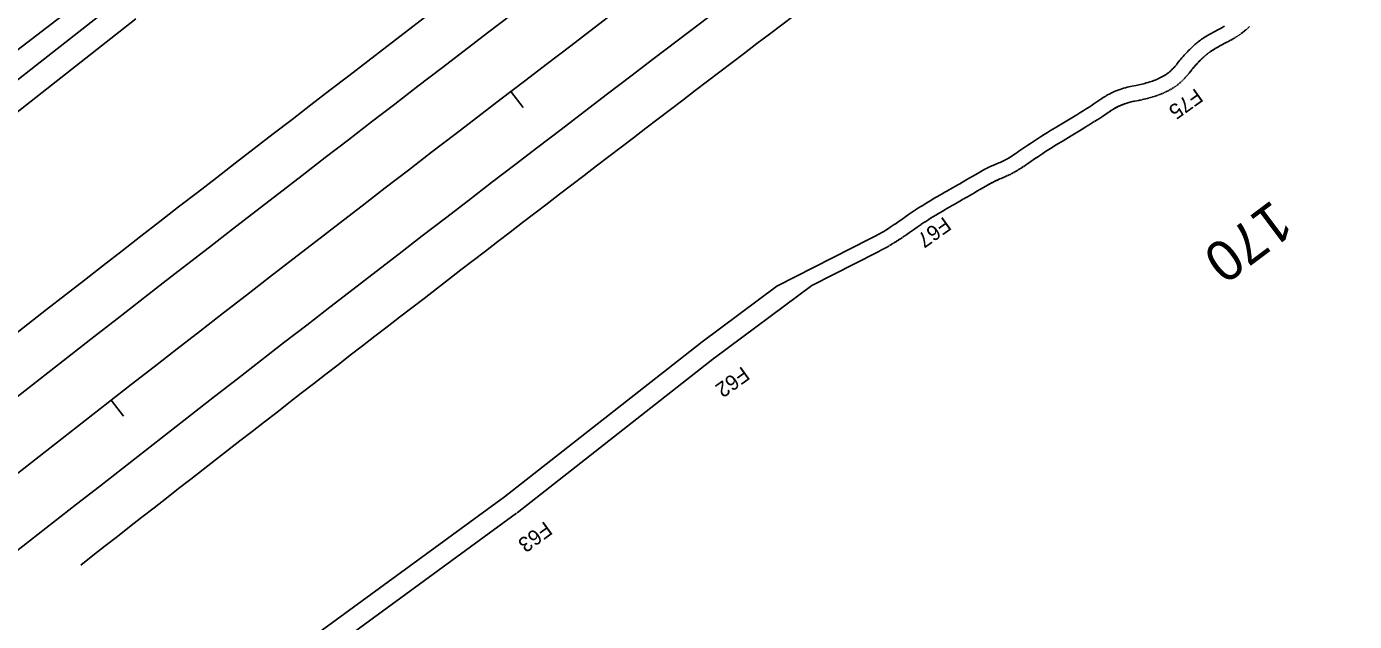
# Model space of a CAD drawing. Extents: x 1469024 to 1473560, y 1105695 to 1109739.
# Drawn here: x 1470861.2 to 1471124.1, y 1107470.7 to 1107588.4 of the extents above; entities that cross this region are included whole.
import ezdxf

# ---------------------------------------------------------------- set-up
doc = ezdxf.new("R2010")
doc.units = 0
for name, color, linetype in [('RD_HC_CL_Rel', 7, 'Continuous'), ('RD_HC_Data_Tic_Rel', 7, 'Continuous'), ('RD_HC_TX_Rel_Sta50', 7, 'Continuous'), ('RD_PD_CstnLmt', 7, 'Continuous'), ('RD_PD_CstnLmt_TX', 7, 'Continuous'), ('RD_PD_DR_Ditch', 7, 'Continuous'), ('RD_PD_DR_ErosCtrl', 7, 'Continuous'), ('RD_PD_Final_TrvlWay', 7, 'Continuous'), ('RD_PD_GR', 7, 'Continuous'), ('RD_PD_RW', 7, 'Continuous')]:
    doc.layers.add(name, color=color, linetype=linetype)

msp = doc.modelspace()

# ---------------------------------------------------------------- linework, layer by layer
at = {"layer": 'RD_HC_CL_Rel'}
msp.add_arc((1477943.58, 1098441.09), 11500, 126.41418, 130.102414, dxfattribs=at)
at = {"layer": 'RD_HC_Data_Tic_Rel'}
for p, q in [((1470957.06, 1107575.56), (1470959.49, 1107572.38)), ((1470877.89, 1107514.46), (1470880.35, 1107511.31))]:
    msp.add_line(p, q, dxfattribs=at)
at = {"layer": 'RD_PD_CstnLmt'}
for p, q in [((1470837.12, 1107566.82), (1470877.09, 1107597.35)), ((1471098.39, 1107588.48), (1471098.12, 1107588.33)), ((1471093.63, 1107585.74), (1471093.38, 1107585.56)), ((1471093.84, 1107585.89), (1471093.63, 1107585.74)), ((1471094.06, 1107586.04), (1471093.84, 1107585.89)), ((1471094.3, 1107586.2), (1471094.06, 1107586.04)), ((1471094.55, 1107586.36), (1471094.3, 1107586.2)), ((1471094.8, 1107586.52), (1471094.55, 1107586.36)), ((1471094.98, 1107586.62), (1471094.8, 1107586.52)), ((1471095.15, 1107586.72), (1471094.98, 1107586.62)), ((1471095.33, 1107586.82), (1471095.15, 1107586.72)), ((1471095.71, 1107587.03), (1471095.33, 1107586.82)), ((1471096.18, 1107587.28), (1471095.71, 1107587.03)), ((1471097.29, 1107587.88), (1471096.18, 1107587.28)), ((1471097.85, 1107588.17), (1471097.29, 1107587.88)), ((1471098.12, 1107588.33), (1471097.85, 1107588.17)), ((1471090.81, 1107583.2), (1471090.6, 1107582.97)), ((1471091.03, 1107583.43), (1471090.81, 1107583.2)), ((1471091.25, 1107583.65), (1471091.03, 1107583.43)), ((1471091.47, 1107583.87), (1471091.25, 1107583.65)), ((1471091.69, 1107584.08), (1471091.47, 1107583.87)), ((1471091.89, 1107584.28), (1471091.69, 1107584.08)), ((1471092.09, 1107584.47), (1471091.89, 1107584.28)), ((1471092.29, 1107584.65), (1471092.09, 1107584.47)), ((1471092.49, 1107584.83), (1471092.29, 1107584.65)), ((1471092.69, 1107585), (1471092.49, 1107584.83)), ((1471092.89, 1107585.16), (1471092.69, 1107585)), ((1471093.01, 1107585.27), (1471092.89, 1107585.16)), ((1471093.14, 1107585.37), (1471093.01, 1107585.27)), ((1471093.38, 1107585.56), (1471093.14, 1107585.37)), ((1471088.52, 1107580.49), (1471088.38, 1107580.33)), ((1471088.65, 1107580.65), (1471088.52, 1107580.49)), ((1471088.83, 1107580.86), (1471088.65, 1107580.65)), ((1471089.01, 1107581.08), (1471088.83, 1107580.86)), ((1471089.54, 1107581.74), (1471089.01, 1107581.08)), ((1471089.72, 1107581.97), (1471089.54, 1107581.74)), ((1471089.94, 1107582.23), (1471089.72, 1107581.97)), ((1471090.16, 1107582.48), (1471089.94, 1107582.23)), ((1471090.39, 1107582.74), (1471090.16, 1107582.48)), ((1471090.6, 1107582.97), (1471090.39, 1107582.74)), ((1471084.89, 1107577.93), (1471084.61, 1107577.81)), ((1471085.2, 1107578.06), (1471084.89, 1107577.93)), ((1471085.45, 1107578.18), (1471085.2, 1107578.06)), ((1471085.7, 1107578.3), (1471085.45, 1107578.18)), ((1471085.95, 1107578.43), (1471085.7, 1107578.3)), ((1471086.2, 1107578.56), (1471085.95, 1107578.43)), ((1471086.45, 1107578.7), (1471086.2, 1107578.56)), ((1471086.57, 1107578.78), (1471086.45, 1107578.7)), ((1471086.69, 1107578.85), (1471086.57, 1107578.78)), ((1471086.81, 1107578.93), (1471086.69, 1107578.85)), ((1471086.93, 1107579.01), (1471086.81, 1107578.93)), ((1471087.04, 1107579.09), (1471086.93, 1107579.01)), ((1471087.16, 1107579.18), (1471087.04, 1107579.09)), ((1471087.27, 1107579.26), (1471087.16, 1107579.18)), ((1471087.38, 1107579.35), (1471087.27, 1107579.26)), ((1471087.49, 1107579.44), (1471087.38, 1107579.35)), ((1471087.6, 1107579.54), (1471087.49, 1107579.44)), ((1471087.7, 1107579.63), (1471087.6, 1107579.54)), ((1471087.81, 1107579.73), (1471087.7, 1107579.63)), ((1471087.95, 1107579.87), (1471087.81, 1107579.73)), ((1471088.09, 1107580.02), (1471087.95, 1107579.87)), ((1471088.24, 1107580.17), (1471088.09, 1107580.02)), ((1471088.38, 1107580.33), (1471088.24, 1107580.17)), ((1471075.99, 1107575.28), (1471075.78, 1107575.18)), ((1471076.2, 1107575.38), (1471075.99, 1107575.28)), ((1471076.4, 1107575.47), (1471076.2, 1107575.38)), ((1471076.61, 1107575.56), (1471076.4, 1107575.47)), ((1471076.87, 1107575.66), (1471076.61, 1107575.56)), ((1471077.13, 1107575.77), (1471076.87, 1107575.66)), ((1471077.41, 1107575.87), (1471077.13, 1107575.77)), ((1471077.72, 1107575.98), (1471077.41, 1107575.87)), ((1471078.05, 1107576.09), (1471077.72, 1107575.98)), ((1471078.39, 1107576.2), (1471078.05, 1107576.09)), ((1471078.74, 1107576.3), (1471078.39, 1107576.2)), ((1471079.09, 1107576.39), (1471078.74, 1107576.3)), ((1471079.44, 1107576.48), (1471079.09, 1107576.39)), ((1471079.72, 1107576.54), (1471079.44, 1107576.48)), ((1471080, 1107576.6), (1471079.72, 1107576.54)), ((1471080.84, 1107576.75), (1471080, 1107576.6)), ((1471081.12, 1107576.81), (1471080.84, 1107576.75)), ((1471081.43, 1107576.87), (1471081.12, 1107576.81)), ((1471081.73, 1107576.94), (1471081.43, 1107576.87)), ((1471082.03, 1107577.01), (1471081.73, 1107576.94)), ((1471082.32, 1107577.08), (1471082.03, 1107577.01)), ((1471082.61, 1107577.16), (1471082.32, 1107577.08)), ((1471082.88, 1107577.24), (1471082.61, 1107577.16)), ((1471083.22, 1107577.34), (1471082.88, 1107577.24)), ((1471083.55, 1107577.44), (1471083.22, 1107577.34)), ((1471083.87, 1107577.54), (1471083.55, 1107577.44)), ((1471084.09, 1107577.62), (1471083.87, 1107577.54)), ((1471084.36, 1107577.72), (1471084.09, 1107577.62)), ((1471084.61, 1107577.81), (1471084.36, 1107577.72)), ((1471071.95, 1107572.75), (1471071.54, 1107572.48)), ((1471072.52, 1107573.13), (1471071.95, 1107572.75)), ((1471073.68, 1107573.9), (1471072.52, 1107573.13)), ((1471074.1, 1107574.19), (1471073.68, 1107573.9)), ((1471074.35, 1107574.34), (1471074.1, 1107574.19)), ((1471074.59, 1107574.5), (1471074.35, 1107574.34)), ((1471074.84, 1107574.66), (1471074.59, 1107574.5)), ((1471075.09, 1107574.8), (1471074.84, 1107574.66)), ((1471075.34, 1107574.95), (1471075.09, 1107574.8)), ((1471075.56, 1107575.06), (1471075.34, 1107574.95)), ((1471075.78, 1107575.18), (1471075.56, 1107575.06)), ((1471068.13, 1107570.36), (1471066.47, 1107569.36)), ((1471069.12, 1107570.96), (1471068.13, 1107570.36)), ((1471069.75, 1107571.35), (1471069.12, 1107570.96)), ((1471070.38, 1107571.74), (1471069.75, 1107571.35)), ((1471070.98, 1107572.12), (1471070.38, 1107571.74)), ((1471071.54, 1107572.48), (1471070.98, 1107572.12)), ((1471063.34, 1107567.47), (1471062.64, 1107567.03)), ((1471063.93, 1107567.83), (1471063.34, 1107567.47)), ((1471064.85, 1107568.39), (1471063.93, 1107567.83)), ((1471066.47, 1107569.36), (1471064.85, 1107568.39)), ((1471059.45, 1107564.95), (1471057.65, 1107563.72)), ((1471060.12, 1107565.4), (1471059.45, 1107564.95)), ((1471060.73, 1107565.81), (1471060.12, 1107565.4)), ((1471061.31, 1107566.19), (1471060.73, 1107565.81)), ((1471061.96, 1107566.61), (1471061.31, 1107566.19)), ((1471062.64, 1107567.03), (1471061.96, 1107566.61)), ((1471055.18, 1107562.15), (1471054.98, 1107562.04)), ((1471055.37, 1107562.26), (1471055.18, 1107562.15)), ((1471055.58, 1107562.38), (1471055.37, 1107562.26)), ((1471055.9, 1107562.57), (1471055.58, 1107562.38)), ((1471056.23, 1107562.78), (1471055.9, 1107562.57)), ((1471056.58, 1107563), (1471056.23, 1107562.78)), ((1471056.93, 1107563.23), (1471056.58, 1107563)), ((1471057.29, 1107563.47), (1471056.93, 1107563.23)), ((1471057.65, 1107563.72), (1471057.29, 1107563.47)), ((1471049.61, 1107559.43), (1471048.55, 1107558.83)), ((1471050.28, 1107559.8), (1471049.61, 1107559.43)), ((1471050.61, 1107559.99), (1471050.28, 1107559.8)), ((1471050.94, 1107560.16), (1471050.61, 1107559.99)), ((1471051.27, 1107560.34), (1471050.94, 1107560.16)), ((1471051.59, 1107560.5), (1471051.27, 1107560.34)), ((1471051.73, 1107560.57), (1471051.59, 1107560.5)), ((1471052.02, 1107560.71), (1471051.73, 1107560.57)), ((1471052.3, 1107560.84), (1471052.02, 1107560.71)), ((1471052.7, 1107561.01), (1471052.3, 1107560.84)), ((1471052.95, 1107561.12), (1471052.7, 1107561.01)), ((1471053.7, 1107561.44), (1471052.95, 1107561.12)), ((1471053.94, 1107561.54), (1471053.7, 1107561.44)), ((1471054.19, 1107561.65), (1471053.94, 1107561.54)), ((1471054.44, 1107561.77), (1471054.19, 1107561.65)), ((1471054.71, 1107561.9), (1471054.44, 1107561.77)), ((1471054.98, 1107562.04), (1471054.71, 1107561.9)), ((1471045.22, 1107556.89), (1471044.49, 1107556.48)), ((1471045.59, 1107557.11), (1471045.22, 1107556.89)), ((1471045.95, 1107557.32), (1471045.59, 1107557.11)), ((1471047.34, 1107558.13), (1471045.95, 1107557.32)), ((1471047.83, 1107558.42), (1471047.34, 1107558.13)), ((1471048.55, 1107558.83), (1471047.83, 1107558.42)), ((1471041.03, 1107554.49), (1471040.08, 1107553.92)), ((1471041.51, 1107554.77), (1471041.03, 1107554.49)), ((1471042, 1107555.06), (1471041.51, 1107554.77)), ((1471042.49, 1107555.34), (1471042, 1107555.06)), ((1471042.97, 1107555.62), (1471042.49, 1107555.34)), ((1471043.36, 1107555.84), (1471042.97, 1107555.62)), ((1471044.49, 1107556.48), (1471043.36, 1107555.84)), ((1471036.58, 1107551.73), (1471036.19, 1107551.46)), ((1471036.99, 1107552), (1471036.58, 1107551.73)), ((1471037.39, 1107552.26), (1471036.99, 1107552)), ((1471037.8, 1107552.52), (1471037.39, 1107552.26)), ((1471038.21, 1107552.78), (1471037.8, 1107552.52)), ((1471038.61, 1107553.03), (1471038.21, 1107552.78)), ((1471039.08, 1107553.31), (1471038.61, 1107553.03)), ((1471040.08, 1107553.92), (1471039.08, 1107553.31)), ((1471032.57, 1107548.95), (1471032.18, 1107548.69)), ((1471032.96, 1107549.21), (1471032.57, 1107548.95)), ((1471033.36, 1107549.47), (1471032.96, 1107549.21)), ((1471033.76, 1107549.75), (1471033.36, 1107549.47)), ((1471034.27, 1107550.1), (1471033.76, 1107549.75)), ((1471035.03, 1107550.64), (1471034.27, 1107550.1)), ((1471035.8, 1107551.19), (1471035.03, 1107550.64)), ((1471036.19, 1107551.46), (1471035.8, 1107551.19)), ((1471028.16, 1107546.38), (1471009.75, 1107537.03)), ((1471028.55, 1107546.59), (1471028.16, 1107546.38)), ((1471028.94, 1107546.79), (1471028.55, 1107546.59)), ((1471029.31, 1107546.99), (1471028.94, 1107546.79)), ((1471029.68, 1107547.2), (1471029.31, 1107546.99)), ((1471030.04, 1107547.39), (1471029.68, 1107547.2)), ((1471030.48, 1107547.65), (1471030.04, 1107547.39)), ((1471030.89, 1107547.89), (1471030.48, 1107547.65)), ((1471031.29, 1107548.14), (1471030.89, 1107547.89)), ((1471031.8, 1107548.45), (1471031.29, 1107548.14)), ((1471032.18, 1107548.69), (1471031.8, 1107548.45)), ((1471009.75, 1107537.03), (1470994.94, 1107526.04)), ((1470994.94, 1107526.04), (1470955.81, 1107495.34)), ((1470955.81, 1107495.34), (1470915.62, 1107466.03))]:
    msp.add_line(p, q, dxfattribs=at)
at = {"layer": 'RD_PD_DR_Ditch'}
for p, q in [((1470840.22, 1107562.84), (1470879.75, 1107593.9)), ((1470843.29, 1107558.9), (1470882.8, 1107589.94))]:
    msp.add_line(p, q, dxfattribs=at)
at = {"layer": 'RD_PD_DR_ErosCtrl'}
for p, q in [((1471103.33, 1107588.39), (1471102.89, 1107588)), ((1471099.86, 1107585.86), (1471099.59, 1107585.71)), ((1471100.06, 1107585.97), (1471099.89, 1107585.88)), ((1471100.25, 1107586.09), (1471100.08, 1107585.99)), ((1471100.44, 1107586.2), (1471100.27, 1107586.1)), ((1471100.63, 1107586.32), (1471100.47, 1107586.22)), ((1471100.82, 1107586.44), (1471100.66, 1107586.34)), ((1471101.02, 1107586.57), (1471100.86, 1107586.46)), ((1471101.21, 1107586.7), (1471101.06, 1107586.59)), ((1471101.41, 1107586.83), (1471101.25, 1107586.73)), ((1471101.6, 1107586.97), (1471101.44, 1107586.86)), ((1471101.79, 1107587.11), (1471101.63, 1107587)), ((1471101.98, 1107587.26), (1471101.82, 1107587.14)), ((1471102.17, 1107587.41), (1471102.01, 1107587.28)), ((1471102.31, 1107587.52), (1471102.2, 1107587.43)), ((1471102.58, 1107587.75), (1471102.35, 1107587.55)), ((1471102.86, 1107587.98), (1471102.62, 1107587.77)), ((1471095.22, 1107583.19), (1471094.98, 1107583)), ((1471095.42, 1107583.33), (1471095.17, 1107583.15)), ((1471095.59, 1107583.45), (1471095.37, 1107583.3)), ((1471095.77, 1107583.58), (1471095.55, 1107583.43)), ((1471095.96, 1107583.71), (1471095.72, 1107583.55)), ((1471096.16, 1107583.83), (1471095.92, 1107583.68)), ((1471096.37, 1107583.96), (1471096.12, 1107583.8)), ((1471096.5, 1107584.04), (1471096.33, 1107583.93)), ((1471096.65, 1107584.12), (1471096.48, 1107584.02)), ((1471096.81, 1107584.21), (1471096.63, 1107584.11)), ((1471097.16, 1107584.4), (1471096.78, 1107584.2)), ((1471097.6, 1107584.64), (1471097.13, 1107584.39)), ((1471098.7, 1107585.23), (1471097.58, 1107584.63)), ((1471099.27, 1107585.53), (1471098.72, 1107585.24)), ((1471099.57, 1107585.7), (1471099.29, 1107585.55)), ((1471092.44, 1107580.53), (1471092.21, 1107580.27)), ((1471092.63, 1107580.75), (1471092.41, 1107580.5)), ((1471092.82, 1107580.95), (1471092.61, 1107580.72)), ((1471093, 1107581.15), (1471092.79, 1107580.92)), ((1471093.2, 1107581.35), (1471092.98, 1107581.12)), ((1471093.39, 1107581.55), (1471093.17, 1107581.33)), ((1471093.59, 1107581.74), (1471093.37, 1107581.53)), ((1471093.78, 1107581.94), (1471093.56, 1107581.72)), ((1471093.96, 1107582.11), (1471093.76, 1107581.92)), ((1471094.14, 1107582.28), (1471093.94, 1107582.09)), ((1471094.32, 1107582.44), (1471094.12, 1107582.25)), ((1471094.49, 1107582.59), (1471094.29, 1107582.41)), ((1471094.66, 1107582.73), (1471094.46, 1107582.56)), ((1471094.82, 1107582.87), (1471094.62, 1107582.7)), ((1471094.91, 1107582.95), (1471094.79, 1107582.84)), ((1471095.01, 1107583.03), (1471094.89, 1107582.93)), ((1471090.25, 1107577.93), (1471090.1, 1107577.78)), ((1471090.43, 1107578.13), (1471090.29, 1107577.97)), ((1471090.61, 1107578.32), (1471090.47, 1107578.17)), ((1471090.78, 1107578.52), (1471090.64, 1107578.36)), ((1471090.94, 1107578.71), (1471090.8, 1107578.55)), ((1471091.14, 1107578.95), (1471090.97, 1107578.74)), ((1471091.34, 1107579.19), (1471091.16, 1107578.97)), ((1471091.88, 1107579.86), (1471091.34, 1107579.2)), ((1471092.04, 1107580.07), (1471091.86, 1107579.84)), ((1471092.24, 1107580.3), (1471092.02, 1107580.04)), ((1471086.38, 1107575.31), (1471086.08, 1107575.17)), ((1471086.69, 1107575.45), (1471086.44, 1107575.33)), ((1471087, 1107575.59), (1471086.75, 1107575.47)), ((1471087.32, 1107575.75), (1471087.06, 1107575.62)), ((1471087.63, 1107575.92), (1471087.38, 1107575.79)), ((1471087.95, 1107576.1), (1471087.7, 1107575.96)), ((1471088.13, 1107576.21), (1471088.01, 1107576.14)), ((1471088.29, 1107576.32), (1471088.17, 1107576.24)), ((1471088.45, 1107576.42), (1471088.33, 1107576.34)), ((1471088.62, 1107576.53), (1471088.5, 1107576.45)), ((1471088.78, 1107576.65), (1471088.66, 1107576.56)), ((1471088.94, 1107576.76), (1471088.83, 1107576.68)), ((1471089.1, 1107576.89), (1471088.99, 1107576.8)), ((1471089.26, 1107577.01), (1471089.15, 1107576.92)), ((1471089.41, 1107577.14), (1471089.3, 1107577.05)), ((1471089.57, 1107577.27), (1471089.46, 1107577.18)), ((1471089.72, 1107577.41), (1471089.61, 1107577.31)), ((1471089.87, 1107577.55), (1471089.76, 1107577.45)), ((1471090.06, 1107577.73), (1471089.91, 1107577.59)), ((1471077.32, 1107572.59), (1471077.1, 1107572.48)), ((1471077.47, 1107572.66), (1471077.27, 1107572.57)), ((1471077.63, 1107572.73), (1471077.42, 1107572.64)), ((1471077.79, 1107572.8), (1471077.58, 1107572.71)), ((1471078, 1107572.89), (1471077.74, 1107572.78)), ((1471078.22, 1107572.97), (1471077.95, 1107572.87)), ((1471078.45, 1107573.06), (1471078.17, 1107572.95)), ((1471078.72, 1107573.15), (1471078.41, 1107573.04)), ((1471079.01, 1107573.25), (1471078.68, 1107573.14)), ((1471079.29, 1107573.34), (1471078.95, 1107573.23)), ((1471079.58, 1107573.42), (1471079.23, 1107573.32)), ((1471079.86, 1107573.5), (1471079.52, 1107573.4)), ((1471080.14, 1107573.56), (1471079.79, 1107573.48)), ((1471080.36, 1107573.61), (1471080.08, 1107573.55)), ((1471080.59, 1107573.65), (1471080.31, 1107573.6)), ((1471081.39, 1107573.8), (1471080.55, 1107573.65)), ((1471081.69, 1107573.86), (1471081.41, 1107573.81)), ((1471082.04, 1107573.93), (1471081.73, 1107573.87)), ((1471082.39, 1107574.01), (1471082.09, 1107573.94)), ((1471082.73, 1107574.09), (1471082.43, 1107574.02)), ((1471083.06, 1107574.18), (1471082.77, 1107574.1)), ((1471083.38, 1107574.26), (1471083.1, 1107574.19)), ((1471083.69, 1107574.35), (1471083.41, 1107574.27)), ((1471084.07, 1107574.46), (1471083.72, 1107574.36)), ((1471084.44, 1107574.57), (1471084.11, 1107574.47)), ((1471084.8, 1107574.69), (1471084.49, 1107574.59)), ((1471085.07, 1107574.79), (1471084.85, 1107574.71)), ((1471085.38, 1107574.9), (1471085.12, 1107574.8)), ((1471085.68, 1107575.01), (1471085.43, 1107574.92)), ((1471086.02, 1107575.15), (1471085.74, 1107575.03)), ((1471073.16, 1107569.96), (1471072.6, 1107569.6)), ((1471073.59, 1107570.23), (1471073.18, 1107569.97)), ((1471074.18, 1107570.62), (1471073.6, 1107570.24)), ((1471075.35, 1107571.41), (1471074.19, 1107570.64)), ((1471075.76, 1107571.69), (1471075.33, 1107571.4)), ((1471075.98, 1107571.83), (1471075.74, 1107571.67)), ((1471076.2, 1107571.97), (1471075.96, 1107571.81)), ((1471076.42, 1107572.1), (1471076.17, 1107571.95)), ((1471076.63, 1107572.23), (1471076.38, 1107572.08)), ((1471076.83, 1107572.34), (1471076.58, 1107572.2)), ((1471076.99, 1107572.43), (1471076.78, 1107572.31)), ((1471077.16, 1107572.51), (1471076.94, 1107572.4)), ((1471069.67, 1107567.79), (1471068.02, 1107566.79)), ((1471070.68, 1107568.4), (1471069.68, 1107567.79)), ((1471071.33, 1107568.8), (1471070.69, 1107568.41)), ((1471071.97, 1107569.2), (1471071.34, 1107568.81)), ((1471072.58, 1107569.59), (1471071.99, 1107569.21)), ((1471064.93, 1107564.92), (1471064.23, 1107564.49)), ((1471065.5, 1107565.28), (1471064.91, 1107564.91)), ((1471066.41, 1107565.82), (1471065.49, 1107565.27)), ((1471068.02, 1107566.79), (1471066.4, 1107565.82)), ((1471061.14, 1107562.47), (1471059.34, 1107561.24)), ((1471061.8, 1107562.92), (1471061.13, 1107562.46)), ((1471062.39, 1107563.31), (1471061.79, 1107562.91)), ((1471062.95, 1107563.68), (1471062.37, 1107563.3)), ((1471063.59, 1107564.08), (1471062.93, 1107563.66)), ((1471064.24, 1107564.5), (1471063.57, 1107564.07)), ((1471056.6, 1107559.51), (1471056.41, 1107559.4)), ((1471056.84, 1107559.64), (1471056.65, 1107559.53)), ((1471057.09, 1107559.78), (1471056.88, 1107559.66)), ((1471057.45, 1107560), (1471057.13, 1107559.81)), ((1471057.83, 1107560.24), (1471057.49, 1107560.03)), ((1471058.21, 1107560.48), (1471057.86, 1107560.26)), ((1471058.58, 1107560.73), (1471058.23, 1107560.5)), ((1471058.96, 1107560.98), (1471058.6, 1107560.74)), ((1471059.33, 1107561.23), (1471058.97, 1107560.99)), ((1471051.1, 1107556.82), (1471050.04, 1107556.22)), ((1471051.74, 1107557.19), (1471051.08, 1107556.82)), ((1471052.05, 1107557.36), (1471051.72, 1107557.18)), ((1471052.36, 1107557.52), (1471052.03, 1107557.35)), ((1471052.66, 1107557.68), (1471052.33, 1107557.51)), ((1471052.95, 1107557.82), (1471052.62, 1107557.66)), ((1471053.06, 1107557.88), (1471052.91, 1107557.81)), ((1471053.31, 1107558), (1471053.03, 1107557.86)), ((1471053.55, 1107558.11), (1471053.27, 1107557.98)), ((1471053.91, 1107558.27), (1471053.51, 1107558.09)), ((1471054.13, 1107558.36), (1471053.88, 1107558.25)), ((1471054.87, 1107558.67), (1471054.12, 1107558.36)), ((1471055.13, 1107558.79), (1471054.89, 1107558.68)), ((1471055.41, 1107558.91), (1471055.16, 1107558.8)), ((1471055.71, 1107559.05), (1471055.46, 1107558.93)), ((1471056.03, 1107559.2), (1471055.76, 1107559.07)), ((1471056.36, 1107559.37), (1471056.09, 1107559.24)), ((1471046.71, 1107554.29), (1471045.97, 1107553.87)), ((1471047.09, 1107554.51), (1471046.72, 1107554.3)), ((1471047.46, 1107554.73), (1471047.1, 1107554.51)), ((1471048.86, 1107555.54), (1471047.47, 1107554.73)), ((1471049.34, 1107555.82), (1471048.84, 1107555.53)), ((1471050.05, 1107556.23), (1471049.33, 1107555.81)), ((1471042.57, 1107551.91), (1471041.62, 1107551.35)), ((1471043.04, 1107552.19), (1471042.56, 1107551.9)), ((1471043.52, 1107552.47), (1471043.03, 1107552.18)), ((1471043.99, 1107552.75), (1471043.5, 1107552.46)), ((1471044.47, 1107553.02), (1471043.98, 1107552.74)), ((1471044.84, 1107553.23), (1471044.46, 1107553.01)), ((1471045.96, 1107553.86), (1471044.83, 1107553.23)), ((1471037.91, 1107549), (1471037.51, 1107548.72)), ((1471038.28, 1107549.25), (1471037.88, 1107548.98)), ((1471038.65, 1107549.5), (1471038.25, 1107549.23)), ((1471039.03, 1107549.75), (1471038.62, 1107549.48)), ((1471039.41, 1107549.99), (1471039.01, 1107549.73)), ((1471039.8, 1107550.24), (1471039.39, 1107549.98)), ((1471040.19, 1107550.48), (1471039.78, 1107550.23)), ((1471040.64, 1107550.75), (1471040.18, 1107550.47)), ((1471041.64, 1107551.35), (1471040.63, 1107550.75)), ((1471034.2, 1107546.43), (1471033.81, 1107546.18)), ((1471034.61, 1107546.7), (1471034.22, 1107546.44)), ((1471035.03, 1107546.98), (1471034.64, 1107546.72)), ((1471035.45, 1107547.27), (1471035.05, 1107547)), ((1471035.98, 1107547.64), (1471035.47, 1107547.28)), ((1471036.76, 1107548.19), (1471036, 1107547.65)), ((1471037.53, 1107548.74), (1471036.76, 1107548.19)), ((1471029.52, 1107543.71), (1471016.65, 1107537.17)), ((1471029.93, 1107543.92), (1471029.54, 1107543.72)), ((1471030.34, 1107544.14), (1471029.95, 1107543.93)), ((1471030.74, 1107544.35), (1471030.36, 1107544.15)), ((1471031.13, 1107544.57), (1471030.76, 1107544.36)), ((1471031.51, 1107544.78), (1471031.15, 1107544.58)), ((1471031.98, 1107545.05), (1471031.54, 1107544.79)), ((1471032.42, 1107545.31), (1471032.01, 1107545.07)), ((1471032.85, 1107545.57), (1471032.44, 1107545.33)), ((1471033.39, 1107545.91), (1471032.88, 1107545.59)), ((1471033.79, 1107546.16), (1471033.41, 1107545.92)), ((1471016.65, 1107537.17), (1470997.32, 1107522.82)), ((1470997.41, 1107522.89), (1470958.28, 1107492.19)), ((1470958.17, 1107492.11), (1470917.97, 1107462.79))]:
    msp.add_line(p, q, dxfattribs=at)
at = {"layer": 'RD_PD_Final_TrvlWay'}
for radius in [11512, 11488]:
    msp.add_arc((1477943.58, 1098441.09), radius, 126.41418, 130.102414, dxfattribs=at)
at = {"layer": 'RD_PD_GR'}
for radius, start, end in [(11522, 127.151906, 128.656189), (11478, 127.050651, 128.032489)]:
    msp.add_arc((1477943.58, 1098441.09), radius, start, end, dxfattribs=at)
at = {"layer": 'RD_PD_RW'}
msp.add_arc((1477943.58, 1098441.09), 11575, 126.41418, 129.547337, dxfattribs=at)

# ---------------------------------------------------------------- texts
at = {"layer": 'RD_HC_TX_Rel_Sta50'}
msp.add_text('170', height=8, rotation=216.9124, dxfattribs=at).set_placement((1471107.85, 1107554.3))
at = {"layer": 'RD_PD_CstnLmt_TX'}
for s, rotation, p in [('F75', 215.4828, (1471092.66, 1107576.3)), ('F67', 215.4828, (1471042.81, 1107550.9)), ('F62', 215.7319, (1471002.9, 1107521.29)), ('F63', 215.981, (1470963.81, 1107490.65))]:
    msp.add_text(s, height=3, rotation=rotation, dxfattribs=at).set_placement(p)

doc.saveas('drawing.dxf')
